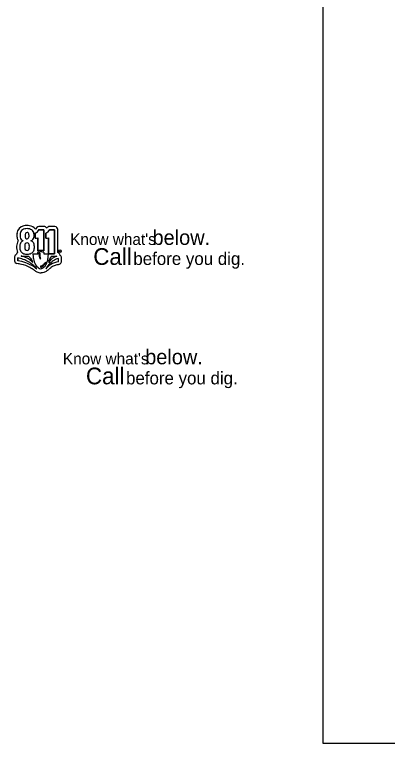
# Model space of a CAD drawing. Extents: x 837 to 1117, y 1316 to 1424.
# Drawn here: x 836.58 to 842.85, y 1398.24 to 1410.48 of the extents above; entities that cross this region are included whole.
import ezdxf

# ---------------------------------------------------------------- set-up
doc = ezdxf.new("R2010")
doc.units = 0
doc.layers.add('0 (Construction)', color=7, linetype='Continuous')
doc.layers.add('Call811-black', color=7, linetype='Continuous')

msp = doc.modelspace()

# ---------------------------------------------------------------- linework, layer by layer
at = {"layer": '0 (Construction)'}
msp.add_lwpolyline([(841.77, 1422.24), (877.77, 1422.24), (877.77, 1398.24), (841.77, 1398.24)], close=True, dxfattribs=at)
at = {"layer": 'Call811-black'}
for p, q in [((836.95, 1406.908), (836.929, 1406.881)), ((837.074, 1406.925), (836.987, 1406.925)), ((837.119, 1406.895), (837.118, 1406.895)), ((837.257, 1406.925), (837.163, 1406.925)), ((836.924, 1406.726), (836.924, 1406.813)), ((836.988, 1406.871), (837.069, 1406.871)), ((837.069, 1406.871), (837.069, 1406.514)), ((837.101, 1406.726), (837.101, 1406.813)), ((837.168, 1406.871), (837.249, 1406.871)), ((837.249, 1406.871), (837.249, 1406.465)), ((837.303, 1406.485), (837.303, 1406.874)), ((836.966, 1406.514), (836.966, 1406.732)), ((837.146, 1406.465), (837.146, 1406.732)), ((836.577, 1406.414), (836.577, 1406.35)), ((836.69, 1406.428), (836.813, 1406.428)), ((836.89, 1406.44), (836.89, 1406.464)), ((836.89, 1406.464), (836.966, 1406.464)), ((836.966, 1406.464), (836.966, 1406.49)), ((837.069, 1406.49), (837.069, 1406.464)), ((837.069, 1406.464), (837.144, 1406.464)), ((837.144, 1406.464), (837.144, 1406.44)), ((837.249, 1406.465), (837.146, 1406.465)), ((837.196, 1406.427), (837.289, 1406.427)), ((836.63, 1406.347), (836.63, 1406.4)), ((837.313, 1406.386), (837.313, 1406.333)), ((837.367, 1406.331), (837.367, 1406.396))]:
    msp.add_line(p, q, dxfattribs=at)
for points in [[(836.95, 1406.908), (836.929, 1406.881)], [(837.074, 1406.925), (836.987, 1406.925)], [(837.119, 1406.895), (837.118, 1406.895)], [(837.257, 1406.925), (837.163, 1406.925)], [(836.924, 1406.813), (836.924, 1406.726)], [(837.069, 1406.514), (837.069, 1406.871), (836.988, 1406.871)], [(837.101, 1406.813), (837.101, 1406.726)], [(837.146, 1406.465), (837.249, 1406.465), (837.249, 1406.871), (837.168, 1406.871)], [(837.303, 1406.485), (837.303, 1406.874)], [(836.966, 1406.732), (836.966, 1406.514)], [(837.146, 1406.732), (837.146, 1406.465)], [(836.577, 1406.414), (836.577, 1406.35)], [(836.69, 1406.428), (836.813, 1406.428)], [(836.89, 1406.44), (836.89, 1406.464), (836.966, 1406.464), (836.966, 1406.49)], [(837.069, 1406.49), (837.069, 1406.464), (837.144, 1406.464), (837.144, 1406.44)], [(837.196, 1406.427), (837.289, 1406.427)], [(836.63, 1406.4), (836.63, 1406.347)], [(837.313, 1406.386), (837.313, 1406.333)], [(837.367, 1406.331), (837.367, 1406.396)], [(837.017, 1406.237), (837.018, 1406.261)]]:
    msp.add_lwpolyline(points, dxfattribs=at)
for radius in [0.0224, 0.0224, 0.0191, 0.0191]:
    msp.add_circle((837.341, 1406.511), radius, dxfattribs=at)
for centre, radius, start, end in [((836.76, 1406.796), 0.143, 99.999, 175.1926), ((836.76, 1406.796), 0.143, 99.999, 175.1926), ((836.788, 1406.622), 0.318, 82.8327, 99.5813), ((836.788, 1406.622), 0.318, 82.8327, 99.5813), ((836.811, 1406.79), 0.149, 37.4108, 83.4439), ((836.811, 1406.79), 0.149, 37.4108, 83.4439), ((836.987, 1406.877), 0.0484, 90.4592, 139.5917), ((836.987, 1406.877), 0.0484, 90.4592, 139.5917), ((837.07, 1406.872), 0.0532, 25.4835, 85.607), ((837.07, 1406.872), 0.0532, 25.4835, 85.607), ((837.167, 1406.871), 0.0538, 94.7078, 153.6211), ((837.167, 1406.871), 0.0538, 94.7078, 153.6211), ((837.25, 1406.872), 0.0534, 2.8738, 82.3381), ((837.25, 1406.872), 0.0534, 2.8738, 82.3381), ((836.871, 1406.773), 0.255, 172.2103, 188.1816), ((836.871, 1406.773), 0.255, 172.2103, 188.1816), ((836.832, 1406.773), 0.163, 168.7247, 190.4792), ((836.832, 1406.773), 0.163, 168.7247, 190.4792), ((836.763, 1406.795), 0.0905, 126.3161, 173.2477), ((836.763, 1406.795), 0.0905, 126.3161, 173.2477), ((836.783, 1406.746), 0.142, 87.8118, 121.4594), ((836.783, 1406.746), 0.142, 87.8118, 121.4594), ((836.886, 1406.771), 0.131, 172.09, 185.2177), ((836.886, 1406.771), 0.131, 172.09, 185.2177), ((836.817, 1406.781), 0.0618, 152.1584, 172.0655), ((836.817, 1406.781), 0.0618, 152.1584, 172.0655), ((836.786, 1406.797), 0.0271, 87.8996, 151.6932), ((836.786, 1406.797), 0.0271, 87.8996, 151.6932), ((836.789, 1406.797), 0.0272, 28.3588, 93.3211), ((836.789, 1406.797), 0.0272, 28.3588, 93.3211), ((836.792, 1406.747), 0.141, 58.4897, 91.5654), ((836.792, 1406.747), 0.141, 58.4897, 91.5654), ((836.758, 1406.781), 0.0618, 7.9345, 27.8416), ((836.758, 1406.781), 0.0618, 7.9345, 27.8416), ((836.69, 1406.771), 0.131, 354.7823, 7.91), ((836.69, 1406.771), 0.131, 354.7823, 7.91), ((836.813, 1406.795), 0.0905, 6.7523, 53.6839), ((836.813, 1406.795), 0.0905, 6.7523, 53.6839), ((836.743, 1406.773), 0.163, 349.5208, 11.2753), ((836.743, 1406.773), 0.163, 349.5208, 11.2753), ((836.866, 1406.941), 0.141, 294.2543, 330.2691), ((836.866, 1406.941), 0.141, 294.2543, 330.2691), ((837.043, 1406.947), 0.147, 293.5734, 328.8767), ((837.043, 1406.947), 0.147, 293.5734, 328.8767), ((836.79, 1406.592), 0.178, 148.69, 179.574), ((836.79, 1406.592), 0.178, 148.69, 179.574), ((836.75, 1406.756), 0.133, 188.1816, 212.2335), ((836.75, 1406.756), 0.133, 188.1816, 212.2335), ((836.77, 1406.598), 0.103, 145.6767, 179.0533), ((836.77, 1406.598), 0.103, 145.6767, 179.0533), ((836.742, 1406.753), 0.07, 187.8977, 254.9735), ((836.742, 1406.753), 0.07, 187.8977, 254.9735), ((836.748, 1406.612), 0.0779, 108.4812, 145.0863), ((836.748, 1406.612), 0.0779, 108.4812, 145.0863), ((836.823, 1406.762), 0.0679, 181.9453, 206.7716), ((836.823, 1406.762), 0.0679, 181.9453, 206.7716), ((836.786, 1406.618), 0.0323, 87.8996, 151.6932), ((836.786, 1406.618), 0.0323, 87.8996, 151.6932), ((836.788, 1406.745), 0.0292, 209.2686, 270.3024), ((836.788, 1406.745), 0.0292, 209.2686, 270.3024), ((836.789, 1406.618), 0.0324, 28.3588, 93.3211), ((836.789, 1406.618), 0.0324, 28.3588, 93.3211), ((836.787, 1406.745), 0.0293, 271.4639, 330.7182), ((836.787, 1406.745), 0.0293, 271.4639, 330.7182), ((836.752, 1406.762), 0.0679, 333.2284, 358.0547), ((836.752, 1406.762), 0.0679, 333.2284, 358.0547), ((836.834, 1406.753), 0.07, 285.0265, 352.1023), ((836.834, 1406.753), 0.07, 285.0265, 352.1023), ((836.827, 1406.612), 0.0779, 34.9137, 71.5188), ((836.827, 1406.612), 0.0779, 34.9137, 71.5188), ((836.806, 1406.598), 0.103, 0.9467, 34.3233), ((836.806, 1406.598), 0.103, 0.9467, 34.3233), ((836.934, 1406.815), 0.0887, 263.562, 290.9659), ((836.934, 1406.815), 0.0887, 263.562, 290.9659), ((837.112, 1406.825), 0.0988, 263.8986, 289.847), ((837.112, 1406.825), 0.0988, 263.8986, 289.847), ((836.837, 1406.577), 0.226, 175.7868, 203.0663), ((836.837, 1406.577), 0.226, 175.7868, 203.0663), ((836.879, 1406.575), 0.215, 173.4284, 191.4963), ((836.879, 1406.575), 0.215, 173.4284, 191.4963), ((836.762, 1406.558), 0.0963, 195.5875, 233.3016), ((836.762, 1406.558), 0.0963, 195.5875, 233.3016), ((836.904, 1406.588), 0.156, 172.09, 185.2177), ((836.904, 1406.588), 0.156, 172.09, 185.2177), ((836.822, 1406.599), 0.0737, 152.1584, 172.0655), ((836.822, 1406.599), 0.0737, 152.1584, 172.0655), ((836.829, 1406.576), 0.0809, 181.9453, 206.7716), ((836.829, 1406.576), 0.0809, 181.9453, 206.7716), ((836.788, 1406.557), 0.0348, 209.2686, 270.3024), ((836.788, 1406.557), 0.0348, 209.2686, 270.3024), ((836.787, 1406.557), 0.0349, 271.4639, 330.7182), ((836.787, 1406.557), 0.0349, 271.4639, 330.7182), ((836.752, 1406.599), 0.0737, 7.9345, 27.8416), ((836.752, 1406.599), 0.0737, 7.9345, 27.8416), ((836.745, 1406.576), 0.0809, 333.2284, 358.0547), ((836.745, 1406.576), 0.0809, 333.2284, 358.0547), ((836.67, 1406.588), 0.156, 354.7823, 7.91), ((836.67, 1406.588), 0.156, 354.7823, 7.91), ((836.813, 1406.558), 0.0963, 306.6984, 344.4125), ((836.813, 1406.558), 0.0963, 306.6984, 344.4125), ((836.696, 1406.575), 0.215, 348.5037, 6.5716), ((836.696, 1406.575), 0.215, 348.5037, 6.5716), ((836.63, 1406.407), 0.0539, 110.5293, 173.0158), ((836.63, 1406.407), 0.0539, 110.5293, 173.0158), ((836.65, 1406.456), 0.0386, 122.909, 178.0418), ((836.65, 1406.456), 0.0386, 122.909, 178.0418), ((836.595, 1406.028), 0.412, 62.33, 76.6551), ((836.595, 1406.028), 0.412, 62.33, 76.6551), ((836.771, 1406.581), 0.12, 236.207, 265.1802), ((836.771, 1406.581), 0.12, 236.207, 265.1802), ((836.786, 1406.646), 0.186, 262.4451, 271.0167), ((836.786, 1406.646), 0.186, 262.4451, 271.0167), ((836.79, 1406.64), 0.18, 269.5148, 277.6277), ((836.79, 1406.64), 0.18, 269.5148, 277.6277), ((836.637, 1406.233), 0.263, 19.3184, 47.9077), ((836.637, 1406.233), 0.263, 19.3184, 47.9077), ((836.804, 1406.581), 0.12, 274.8198, 303.793), ((836.804, 1406.581), 0.12, 274.8198, 303.793), ((837.254, 1406.442), 0.364, 180.4178, 193.2572), ((837.254, 1406.442), 0.364, 180.4178, 193.2572), ((836.989, 1406.466), 0.0538, 98.3212, 116.1927), ((836.989, 1406.466), 0.0538, 98.3212, 116.1927), ((836.989, 1406.441), 0.0538, 98.3212, 116.1927), ((836.989, 1406.441), 0.0538, 98.3212, 116.1927), ((837.014, 1406.326), 0.196, 88.3567, 99.6507), ((837.014, 1406.326), 0.196, 88.3567, 99.6507), ((837.014, 1406.301), 0.196, 88.3567, 99.6507), ((837.014, 1406.301), 0.196, 88.3567, 99.6507), ((836.998, 1406.441), 0.0372, 82.0234, 112.2206), ((837.179, 1406.473), 0.195, 179.2441, 210.2904), ((837.591, 1406.468), 0.588, 179.0296, 189.1158), ((837.022, 1406.336), 0.186, 80.2121, 90.547), ((837.022, 1406.336), 0.186, 80.2121, 90.547), ((837.022, 1406.312), 0.186, 80.2121, 90.547), ((837.022, 1406.312), 0.186, 80.2121, 90.547), ((837.046, 1406.466), 0.0538, 63.8073, 81.6788), ((837.046, 1406.466), 0.0538, 63.8073, 81.6788), ((837.046, 1406.441), 0.0538, 63.8073, 81.6788), ((837.046, 1406.441), 0.0538, 63.8073, 81.6788), ((836.78, 1406.442), 0.364, 346.7428, 359.5822), ((836.78, 1406.442), 0.364, 346.7428, 359.5822), ((837.361, 1406.189), 0.249, 106.8433, 148.53), ((837.428, 1406.262), 0.285, 144.6348, 168.4777), ((837.361, 1406.189), 0.249, 106.8433, 148.53), ((837.428, 1406.262), 0.285, 144.6348, 168.4777), ((837.287, 1406.424), 0.0631, 53.7627, 75.1967), ((837.287, 1406.424), 0.0631, 53.7627, 75.1967), ((837.285, 1406.43), 0.0594, 7.3834, 48.7359), ((837.285, 1406.43), 0.0594, 7.3834, 48.7359), ((837.317, 1406.396), 0.0499, 0.2357, 57.1812), ((837.317, 1406.396), 0.0499, 0.2357, 57.1812), ((836.63, 1406.353), 0.0528, 183.4717, 256.8514), ((836.63, 1406.353), 0.0528, 183.4717, 256.8514), ((836.197, 1403.662), 2.672, 79.3174, 80.9479), ((836.197, 1403.662), 2.672, 79.3174, 80.9479), ((836.534, 1405.883), 0.525, 57.9733, 79.5163), ((836.534, 1405.883), 0.525, 57.9733, 79.5163), ((836.579, 1405.816), 0.533, 69.1311, 84.5007), ((836.579, 1405.816), 0.533, 69.1311, 84.5007), ((836.56, 1405.703), 0.6, 62.6567, 77.1974), ((836.56, 1405.703), 0.6, 62.6567, 77.1974), ((836.558, 1405.723), 0.627, 50.9726, 70.3844), ((836.558, 1405.723), 0.627, 50.9726, 70.3844), ((836.645, 1406.096), 0.329, 43.0467, 64.4523), ((836.645, 1406.096), 0.329, 43.0467, 64.4523), ((836.503, 1405.819), 0.597, 41.0274, 58.6813), ((836.503, 1405.819), 0.597, 41.0274, 58.6813), ((837.119, 1406.399), 0.222, 190.4857, 218.6347), ((837.119, 1406.399), 0.222, 190.4857, 218.6347), ((836.932, 1406.414), 0.196, 295.7354, 319.9002), ((836.988, 1406.379), 0.122, 284.3512, 313.9705), ((836.825, 1406.559), 0.365, 312.7475, 319.6368), ((837.01, 1406.353), 0.0975, 318.3348, 342.4149), ((836.916, 1406.399), 0.222, 321.3653, 349.5143), ((836.916, 1406.399), 0.222, 321.3653, 349.5143), ((837.466, 1405.999), 0.423, 124.3323, 149.8558), ((837.466, 1405.999), 0.423, 124.3323, 149.8558), ((837.385, 1405.966), 0.376, 122.1554, 139.2439), ((837.385, 1405.966), 0.376, 122.1554, 139.2439), ((837.354, 1406.033), 0.302, 97.6832, 123.9821), ((837.354, 1406.033), 0.302, 97.6832, 123.9821), ((837.354, 1406.176), 0.214, 100.9877, 126.326), ((837.354, 1406.176), 0.214, 100.9877, 126.326), ((837.371, 1405.951), 0.339, 99.6589, 109.4788), ((837.371, 1405.951), 0.339, 99.6589, 109.4788), ((837.306, 1406.355), 0.0698, 276.8288, 293.6655), ((837.306, 1406.355), 0.0698, 276.8288, 293.6655), ((837.316, 1406.339), 0.0518, 290.7825, 351.1469), ((837.316, 1406.339), 0.0518, 290.7825, 351.1469), ((835.849, 1404.617), 1.896, 56.1356, 58.6515), ((835.849, 1404.617), 1.896, 56.1356, 58.6515), ((837.048, 1406.377), 0.234, 232.4217, 246.1444), ((837.048, 1406.377), 0.234, 232.4217, 246.1444), ((837.061, 1406.351), 0.147, 217.9711, 252.8236), ((837.061, 1406.351), 0.147, 217.9711, 252.8236), ((837.017, 1406.295), 0.147, 244.4852, 271.9359), ((837.017, 1406.295), 0.147, 244.4852, 271.9359), ((836.974, 1406.351), 0.147, 287.1764, 322.0289), ((836.974, 1406.351), 0.147, 287.1764, 322.0289), ((837.022, 1406.331), 0.182, 269.938, 287.1165), ((837.022, 1406.331), 0.182, 269.938, 287.1165), ((837.002, 1406.354), 0.21, 290.4356, 305.7025), ((837.002, 1406.354), 0.21, 290.4356, 305.7025), ((836.928, 1406.466), 0.345, 304.793, 312.2432), ((836.928, 1406.466), 0.345, 304.793, 312.2432), ((837.382, 1405.96), 0.335, 122.9567, 131.4897), ((837.382, 1405.96), 0.335, 122.9567, 131.4897), ((837.36, 1405.996), 0.293, 110.3424, 123.2327), ((837.36, 1405.996), 0.293, 110.3424, 123.2327)]:
    msp.add_arc(centre, radius, start, end, dxfattribs=at)

# ---------------------------------------------------------------- texts
for s, height, p in [("Know what's", 0.19301, (837.512, 1406.614)), ('below.', 0.2509, (838.897, 1406.615)), ('Call', 0.281, (837.901, 1406.279)), ('R', 0.0236, (837.33, 1406.5)), ('before you dig.', 0.21231, (838.575, 1406.278)), ("Know what's", 0.19301, (837.39, 1404.608)), ('below.', 0.2509, (838.774, 1404.609)), ('Call', 0.281, (837.778, 1404.273)), ('before you dig.', 0.21231, (838.452, 1404.272))]:
    msp.add_text(s, height=height, dxfattribs=at).set_placement(p)

doc.saveas('drawing.dxf')
